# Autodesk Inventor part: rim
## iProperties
Author: Administrator
Shininess: 0.0
PropertySet Name: _Private Model Information
Created: 1999-10
Part Number: rim
Document SubType Name: Modeling
Designer: Administrator
Control State: 0
Master: False
Checked Out: False
PropertySet Name: Design Tracking Control
Density: 0.0
Volumn: 0.0
Area: 0.0
PropertySet Name: Model Information
